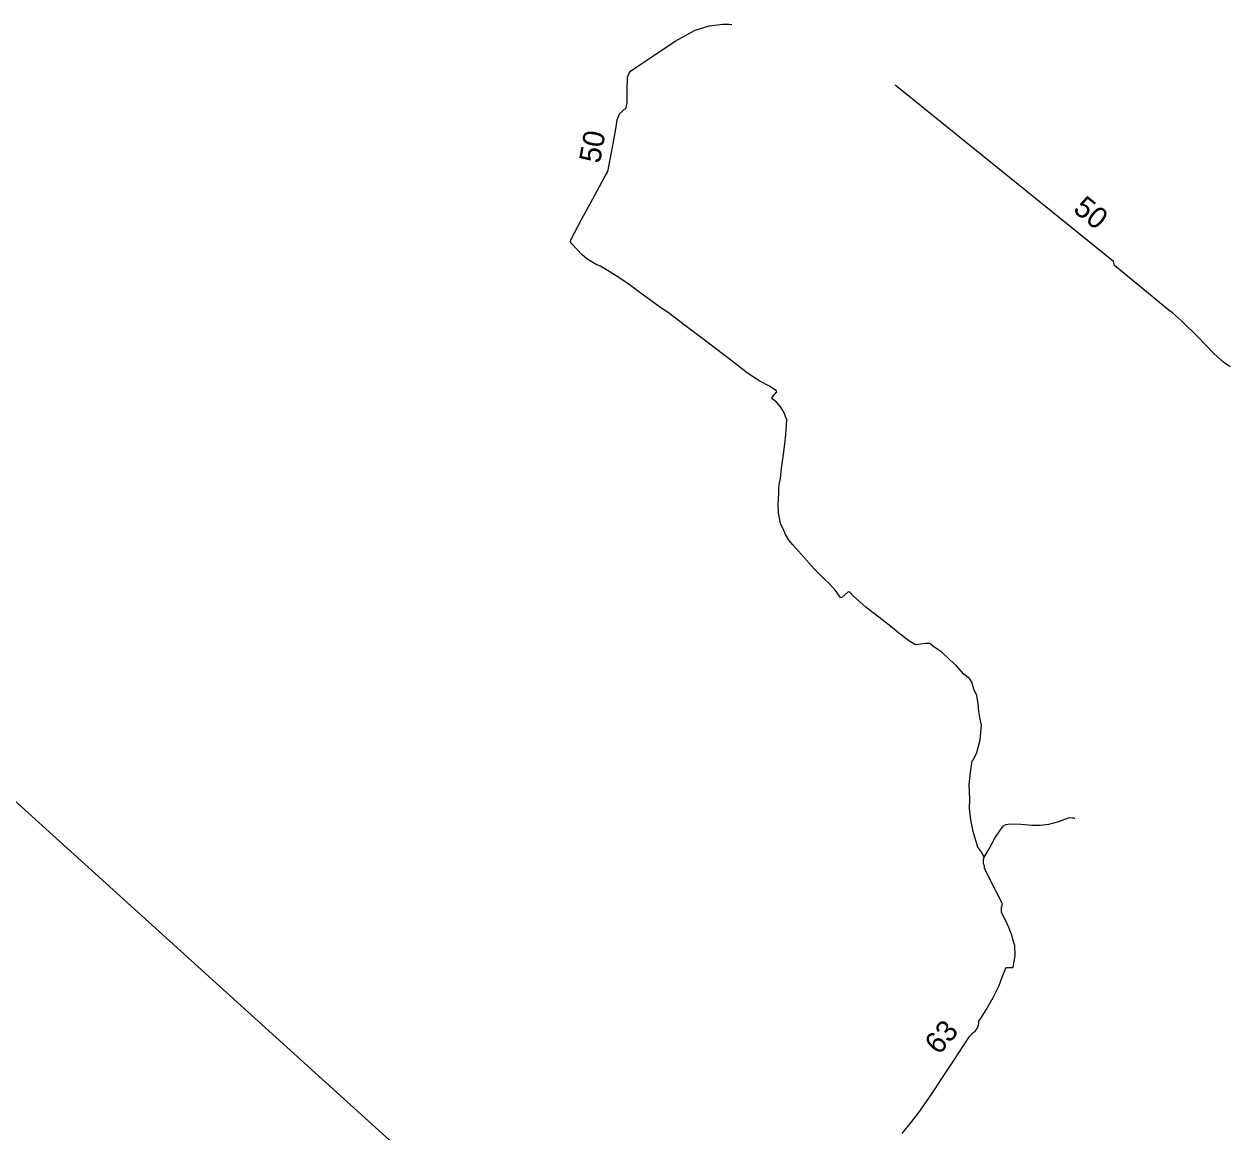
# Model space of a CAD drawing. Extents: x -444817 to -434929, y -1145681 to -1129851.
# Drawn here: x -443162.8 to -442712, y -1130962.1 to -1130546.7 of the extents above; entities that cross this region are included whole.
import ezdxf

# ---------------------------------------------------------------- set-up
doc = ezdxf.new("R2010")
doc.units = 0
for name, color, linetype in [('Vrstva 27', 7, 'Continuous'), ('Vrstva 30', 7, 'Continuous'), ('Vrstva 35', 7, 'Continuous'), ('Vrstva 38', 7, 'Continuous'), ('Vrstva 59', 7, 'Continuous')]:
    doc.layers.add(name, color=color, linetype=linetype)

msp = doc.modelspace()

# ---------------------------------------------------------------- linework, layer by layer
at = {"layer": 'Vrstva 27'}
for points in [[(-442948.46, -1130636.83), (-442951.87, -1130634.68), (-442953.67, -1130633.16), (-442957.48, -1130629.04), (-442958.02, -1130628.37), (-442957.91, -1130627.65), (-442953.91, -1130619.91), (-442949.7, -1130612.21), (-442945.35, -1130604.37), (-442944.09, -1130601.96), (-442943.43, -1130598.8), (-442941.97, -1130590.85), (-442940.93, -1130585.18), (-442940.54, -1130582.6), (-442939.6, -1130580.36), (-442937.16, -1130578.11), (-442936.75, -1130576.27), (-442936.83, -1130571.51), (-442936.69, -1130566.66), (-442936.2, -1130565.3), (-442935.54, -1130564.39), (-442933.22, -1130562.69), (-442927.13, -1130558.77), (-442918.83, -1130553.17), (-442911.3, -1130548.95), (-442906.12, -1130547.37), (-442900.95, -1130546.69), (-442898.69, -1130546.72), (-442897.52, -1130546.8)], [(-442832.8, -1130776.69), (-442835.56, -1130774.5), (-442837.51, -1130772.98), (-442841.34, -1130769.98), (-442847.34, -1130765.3), (-442852.04, -1130761.08), (-442853.33, -1130759.71), (-442853.74, -1130759.58), (-442854.05, -1130759.7), (-442856.16, -1130761.61), (-442856.43, -1130761.77), (-442856.8, -1130761.66), (-442857.2, -1130761.13), (-442858.77, -1130759.04), (-442860.9, -1130756.63), (-442862.96, -1130754.69), (-442866.77, -1130750.91), (-442871.63, -1130745.45), (-442874.71, -1130741.99), (-442876.12, -1130740.32), (-442877.41, -1130738.02), (-442878.05, -1130736.62), (-442879.31, -1130733.89), (-442879.34, -1130733.82), (-442880.12, -1130729.93), (-442880.24, -1130726.64), (-442879.98, -1130722.59), (-442879.93, -1130720.68), (-442879.75, -1130718.71), (-442879.38, -1130717.07), (-442879.03, -1130714.37), (-442878.79, -1130712.29), (-442878.53, -1130710.66), (-442878.17, -1130707.99), (-442877.73, -1130704.1), (-442877.36, -1130700.56), (-442877.06, -1130697.13), (-442876.96, -1130694.99), (-442877.43, -1130693.8), (-442877.65, -1130693.09), (-442878.16, -1130691.99), (-442879.28, -1130690.17), (-442880.76, -1130688.64), (-442882.14, -1130687.3), (-442882.47, -1130686.97), (-442882.39, -1130686.52), (-442880.78, -1130684.71), (-442880.73, -1130684.65), (-442880.87, -1130684.18), (-442881.51, -1130683.78), (-442883.42, -1130682.5), (-442887.04, -1130680.61), (-442889.84, -1130678.89), (-442892.38, -1130677.09), (-442897.92, -1130672.65), (-442903.24, -1130668.76), (-442908.93, -1130664.36), (-442914.87, -1130659.82), (-442919.66, -1130656.15), (-442921.43, -1130654.84), (-442924.16, -1130653.04), (-442927.86, -1130650.36), (-442931.98, -1130647.32), (-442935.48, -1130644.67), (-442939.94, -1130641.73), (-442944.13, -1130639.08), (-442946.77, -1130637.43), (-442948.46, -1130636.83)], [(-442710.88, -1130675.26), (-442713.18, -1130673.54), (-442717, -1130670.16), (-442722.91, -1130663.98), (-442729.07, -1130658), (-442732.37, -1130655.02), (-442733.63, -1130654.08), (-442734.2, -1130653.65)], [(-442833.76, -1130962.64), (-442830.14, -1130958.16), (-442827.51, -1130954.79), (-442826, -1130952.6), (-442825.27, -1130951.56), (-442823.96, -1130949.76), (-442821.41, -1130945.88), (-442820.26, -1130944.13), (-442818.61, -1130941.62), (-442818.36, -1130941.23), (-442814.37, -1130935.29), (-442810.63, -1130929.55), (-442808.52, -1130926.29), (-442807.39, -1130925.01), (-442806.35, -1130924.23), (-442805.65, -1130923.28), (-442805.17, -1130922.08), (-442805.03, -1130921.18), (-442804.98, -1130920.58), (-442804.44, -1130919.67), (-442802.26, -1130916.22), (-442799.64, -1130911.63), (-442797.43, -1130907.11), (-442796.22, -1130904.05), (-442795.03, -1130900.85), (-442794.77, -1130900.47), (-442794.4, -1130900.43), (-442793.6, -1130900.42), (-442793.13, -1130900.43), (-442792.49, -1130900.44), (-442792.31, -1130900.36), (-442792.04, -1130899.8), (-442791.84, -1130898.69), (-442791.73, -1130897.99), (-442791.44, -1130896.02), (-442791.5, -1130892.12), (-442791.98, -1130890.66), (-442792.78, -1130887.95), (-442793.33, -1130886.43), (-442793.81, -1130885.44), (-442795.16, -1130882.39), (-442796.46, -1130879.79), (-442796.56, -1130878.68), (-442796.52, -1130877.84), (-442796.22, -1130877.14), (-442796.24, -1130876.36), (-442796.7, -1130875.34), (-442798.48, -1130871.95), (-442800.6, -1130867.78), (-442802.82, -1130863.18), (-442802.88, -1130862.46), (-442803.26, -1130861.45), (-442803.2, -1130860.18), (-442803.04, -1130858.98), (-442803.2, -1130858.69), (-442803.85, -1130857.32), (-442805.35, -1130855.35), (-442805.9, -1130853.69), (-442807.15, -1130849.37), (-442808.06, -1130845.03), (-442808.48, -1130840.85), (-442808.44, -1130837.12), (-442808.65, -1130831.96), (-442808.19, -1130827.16), (-442807.51, -1130822.86), (-442807.06, -1130822.47), (-442805.77, -1130819.78), (-442804.56, -1130815.08), (-442804.01, -1130809.6), (-442804.58, -1130806.68), (-442805.05, -1130804.47), (-442805.29, -1130801.49), (-442805.78, -1130798.43), (-442806.84, -1130796.11), (-442807.58, -1130793.48), (-442808.51, -1130792.09), (-442810.59, -1130790.46), (-442813.35, -1130787.28), (-442815.89, -1130785.07), (-442818.93, -1130782.19), (-442821.92, -1130780.16), (-442823.4, -1130778.91), (-442825, -1130778.91), (-442826.86, -1130779.16), (-442828.73, -1130779.47), (-442830.85, -1130778.23), (-442832.8, -1130776.69)], [(-442803.04, -1130858.98), (-442801.14, -1130855.89), (-442798.98, -1130851.88), (-442796.91, -1130848.81), (-442795.82, -1130847.35), (-442794.93, -1130846.77), (-442793.32, -1130846.5), (-442789.21, -1130846.72), (-442785.04, -1130847), (-442782.02, -1130847.09), (-442778.78, -1130846.68), (-442775.08, -1130845.69), (-442772.79, -1130844.82), (-442771.01, -1130844.17), (-442770.07, -1130844.26), (-442769.45, -1130844.32), (-442769.07, -1130844.5)]]:
    msp.add_lwpolyline(points, dxfattribs=at)
at = {"layer": 'Vrstva 35'}
msp.add_lwpolyline([(-442733.63, -1130654.08), (-442754.18, -1130637.18), (-442754.49, -1130635.74), (-442836.38, -1130569.65)], dxfattribs=at)
at = {"layer": 'Vrstva 59'}
msp.add_lwpolyline([(-443357.81, -1130664.34), (-442622.23, -1131330.87), (-441886.65, -1131997.4), (-441341.88, -1132491.05)], dxfattribs=at)

# ---------------------------------------------------------------- texts
at = {"layer": 'Vrstva 30'}
for s, rotation, p in [('50', 79.5937, (-442947.02, -1130599.19)), ('63', 48.8408, (-442820.02, -1130933.49))]:
    msp.add_text(s, height=8, rotation=rotation, dxfattribs=at).set_placement(p)
at = {"layer": 'Vrstva 38'}
msp.add_text('50', height=8, rotation=321.0931, dxfattribs=at).set_placement((-442770.07, -1130616.74))

doc.saveas('drawing.dxf')
